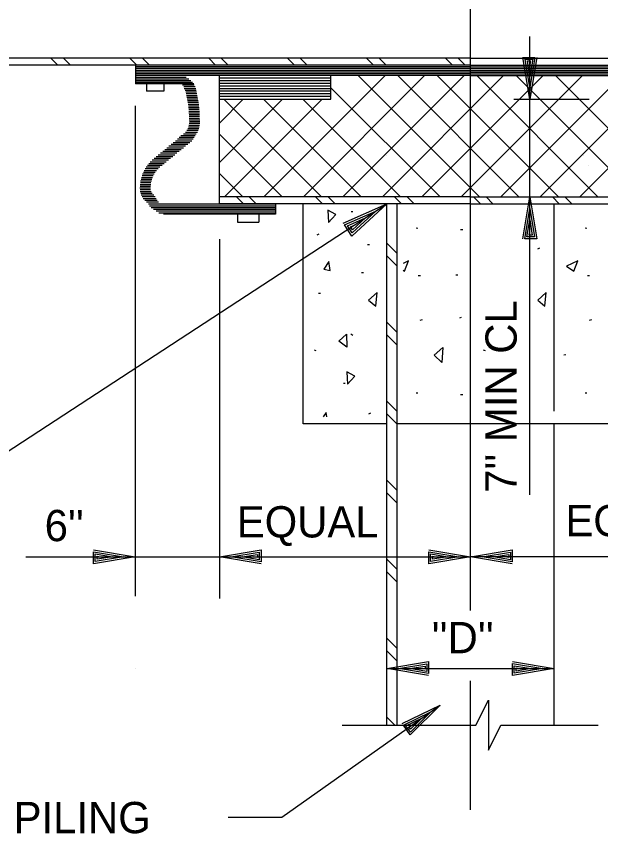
# Model space of a CAD drawing. Extents: x 22339.2 to 22413.4, y 22369.6 to 22418.8.
# Drawn here: x 22343.24 to 22346.729, y 22391.783 to 22396.66 of the extents above; entities that cross this region are included whole.
import ezdxf

# ---------------------------------------------------------------- set-up
doc = ezdxf.new("R2010")
doc.units = 0
for name, color, linetype in [('Level 1', 7, 'Continuous'), ('Level 10', 7, 'Continuous'), ('Level 2', 7, 'Continuous'), ('Level 4', 7, 'Continuous'), ('Level 44', 7, 'Continuous'), ('Level 7', 7, 'Continuous'), ('Level 8', 7, 'Continuous')]:
    doc.layers.add(name, color=color, linetype=linetype)

msp = doc.modelspace()

# ---------------------------------------------------------------- linework, layer by layer
at = {"layer": 'Level 1'}
for p, q in [((22345.9524, 22393.1147), (22345.9524, 22402.6063)), ((22346.3062, 22396.1656), (22346.3062, 22396.54)), ((22344.4524, 22395.5406), (22344.4524, 22396.3063)), ((22345.1191, 22396.2906), (22344.4524, 22396.2906)), ((22345.1191, 22396.275), (22344.4524, 22396.275)), ((22345.1191, 22396.2594), (22344.4524, 22396.2594)), ((22344.0172, 22396.2566), (22344.0172, 22396.2136)), ((22344.1208, 22396.2136), (22344.0172, 22396.2136)), ((22344.1208, 22396.2566), (22344.1208, 22396.2136)), ((22345.1191, 22396.2438), (22344.4524, 22396.2438)), ((22345.1191, 22396.2281), (22344.4524, 22396.2281)), ((22345.1191, 22396.2125), (22344.4524, 22396.2125)), ((22345.1191, 22396.1969), (22344.4524, 22396.1969)), ((22345.1191, 22396.1813), (22344.4524, 22396.1813)), ((22346.2105, 22396.1656), (22346.6612, 22396.1656)), ((22346.3062, 22395.5823), (22346.3062, 22396.1656)), ((22343.9502, 22396.1261), (22343.9502, 22393.1991)), ((22346.3062, 22396.1448), (22346.3062, 22396.1448)), ((22346.3062, 22395.8948), (22346.3062, 22395.8948)), ((22345.4524, 22395.8323), (22345.4524, 22395.8323)), ((22346.3062, 22395.8255), (22346.3062, 22395.8255)), ((22346.6267, 22395.8323), (22346.6267, 22395.8323)), ((22345.3966, 22395.7912), (22345.3966, 22395.7912)), ((22346.6566, 22395.7697), (22346.6566, 22395.7697)), ((22345.9524, 22395.5823), (22344.4524, 22395.5823)), ((22345.9524, 22395.5823), (22347.4524, 22395.5823)), ((22346.3062, 22393.8053), (22346.3062, 22395.5823)), ((22345.9524, 22395.5406), (22344.4524, 22395.5406)), ((22345.9524, 22395.5406), (22347.4524, 22395.5406)), ((22344.5612, 22395.479), (22344.5612, 22395.4313)), ((22344.6886, 22395.479), (22344.6886, 22395.4313)), ((22344.5612, 22395.4313), (22344.6886, 22395.4313)), ((22344.4524, 22395.3296), (22344.4524, 22393.1868)), ((22343.2972, 22393.4347), (22343.9502, 22393.4347)), ((22343.9502, 22393.4347), (22344.4524, 22393.4347)), ((22344.4524, 22393.4347), (22345.9524, 22393.4347)), ((22344.4524, 22393.4347), (22344.4524, 22393.4347)), ((22344.5217, 22393.4347), (22344.5217, 22393.4347)), ((22345.8831, 22393.4347), (22345.8831, 22393.4347)), ((22347.4524, 22393.4347), (22345.9524, 22393.4347)), ((22345.9524, 22393.4347), (22345.9524, 22393.4347)), ((22345.9524, 22393.4347), (22345.9524, 22393.4347)), ((22346.0217, 22393.4347), (22346.0217, 22393.4347)), ((22343.9502, 22392.768), (22343.9502, 22392.768)), ((22345.4524, 22392.768), (22346.4524, 22392.768)), ((22345.8831, 22392.768), (22345.8831, 22392.768)), ((22345.9524, 22392.768), (22345.9524, 22392.768)), ((22345.9524, 22392.768), (22345.9524, 22392.768)), ((22346.0217, 22392.768), (22346.0217, 22392.768)), ((22345.9524, 22391.9249), (22345.9524, 22392.6957)), ((22345.7149, 22392.5096), (22345.7149, 22392.5096)), ((22345.7715, 22392.5496), (22345.7715, 22392.5496)), ((22345.1864, 22392.4303), (22345.9844, 22392.4303)), ((22346.1339, 22392.4303), (22346.7136, 22392.4303))]:
    msp.add_line(p, q, dxfattribs=at)
msp.add_lwpolyline([(22345.9844, 22392.4303), (22346.0589, 22392.5803), (22346.0589, 22392.2806), (22346.1339, 22392.4303)], dxfattribs=at)
at = {"layer": 'Level 10'}
for p, q in [((22342.4783, 22393.5993), (22345.4524, 22395.5406)), ((22345.4524, 22395.5406), (22345.4524, 22395.5406)), ((22345.3871, 22395.498), (22345.3871, 22395.498))]:
    msp.add_line(p, q, dxfattribs=at)
msp.add_lwpolyline([(22345.1921, 22395.4262), (22345.4524, 22395.5406), (22345.2429, 22395.3484), (22345.1995, 22395.4149), (22345.3871, 22395.498), (22345.2448, 22395.3675), (22345.2169, 22395.4102), (22345.3243, 22395.457), (22345.2466, 22395.3866), (22345.2352, 22395.4042), (22345.259, 22395.4144)], dxfattribs=at)
at = {"layer": 'Level 2'}
for p, q in [((22345.9524, 22396.4104), (22339.2566, 22396.4104)), ((22345.9524, 22396.4104), (22352.6356, 22396.4104)), ((22345.9524, 22396.3688), (22339.2869, 22396.3688)), ((22343.9511, 22396.3688), (22343.9511, 22396.2566)), ((22345.9524, 22396.3583), (22343.9511, 22396.3583)), ((22345.9524, 22396.3688), (22352.6121, 22396.3688)), ((22345.9524, 22396.3583), (22347.9537, 22396.3583)), ((22345.9524, 22396.3479), (22343.9511, 22396.3479)), ((22345.9524, 22396.3375), (22343.9511, 22396.3375)), ((22345.9524, 22396.3271), (22343.9511, 22396.3271)), ((22345.9524, 22396.3167), (22343.9511, 22396.3167)), ((22345.9524, 22396.3063), (22343.9511, 22396.3063)), ((22344.4524, 22396.1656), (22344.4524, 22396.3063)), ((22345.1191, 22396.1656), (22345.1191, 22396.3063)), ((22345.9524, 22396.3479), (22347.9537, 22396.3479)), ((22345.9524, 22396.3375), (22347.9537, 22396.3375)), ((22345.9524, 22396.3271), (22347.9537, 22396.3271)), ((22345.9524, 22396.3167), (22347.9537, 22396.3167)), ((22345.9524, 22396.3063), (22347.9537, 22396.3063)), ((22344.2992, 22396.2566), (22343.9511, 22396.2566)), ((22344.4524, 22396.1656), (22345.1191, 22396.1656)), ((22344.7869, 22395.5406), (22344.7869, 22395.479)), ((22345.4524, 22392.4303), (22345.4524, 22395.5406)), ((22345.5149, 22392.4303), (22345.5149, 22395.5406)), ((22346.4524, 22394.3032), (22346.4524, 22395.5406)), ((22344.7869, 22395.479), (22344.1184, 22395.479)), ((22346.4524, 22392.4303), (22346.4524, 22394.2281))]:
    msp.add_line(p, q, dxfattribs=at)
for points in [[(22346.3475, 22396.415), (22346.3062, 22396.1656), (22346.2648, 22396.415), (22346.3355, 22396.415), (22346.3062, 22396.235), (22346.2782, 22396.4043), (22346.3235, 22396.4043), (22346.3062, 22396.3016), (22346.2915, 22396.3936), (22346.3102, 22396.3936), (22346.3062, 22396.371)], [(22344.2344, 22396.3063), (22343.9511, 22396.3063)], [(22344.2549, 22396.2958), (22343.9524, 22396.2958)], [(22344.2702, 22396.2854), (22343.9524, 22396.2854)], [(22344.2826, 22396.275), (22343.9524, 22396.275)], [(22344.2929, 22396.2646), (22343.9524, 22396.2646)], [(22344.3024, 22396.249), (22344.2327, 22396.249)], [(22344.3077, 22396.2386), (22344.2408, 22396.2386)], [(22344.3111, 22396.2281), (22344.2424, 22396.2281)], [(22344.3139, 22396.2177), (22344.2487, 22396.2177)], [(22344.3163, 22396.2073), (22344.2519, 22396.2073)], [(22344.3183, 22396.1969), (22344.2544, 22396.1969)], [(22344.32, 22396.1865), (22344.2566, 22396.1865)], [(22344.3218, 22396.1761), (22344.2584, 22396.1761)], [(22344.3236, 22396.1656), (22344.2602, 22396.1656)], [(22344.3254, 22396.1552), (22344.2619, 22396.1552)], [(22344.3273, 22396.1448), (22344.2638, 22396.1448)], [(22344.329, 22396.1344), (22344.2656, 22396.1344)], [(22344.3305, 22396.124), (22344.2673, 22396.124)], [(22344.3317, 22396.1136), (22344.2687, 22396.1136)], [(22344.3324, 22396.1031), (22344.2698, 22396.1031)], [(22344.333, 22396.0927), (22344.2704, 22396.0927)], [(22344.3336, 22396.0823), (22344.271, 22396.0823)], [(22344.3342, 22396.0719), (22344.2716, 22396.0719)], [(22344.3349, 22396.0511), (22344.2719, 22396.0511)], [(22344.3347, 22396.0615), (22344.2722, 22396.0615)], [(22344.3354, 22396.0198), (22344.2726, 22396.0198)], [(22344.3357, 22396.0406), (22344.2731, 22396.0406)], [(22344.3359, 22396.0302), (22344.2734, 22396.0302)], [(22344.3226, 22395.9677), (22344.2504, 22395.9677)], [(22344.3266, 22395.9781), (22344.2578, 22395.9781)], [(22344.3298, 22395.9886), (22344.2634, 22395.9886)], [(22344.3324, 22395.999), (22344.2677, 22395.999)], [(22344.3342, 22396.0094), (22344.2707, 22396.0094)], [(22344.2875, 22395.9156), (22344.1901, 22395.9156)], [(22344.297, 22395.9261), (22344.2029, 22395.9261)], [(22344.3012, 22395.9365), (22344.2117, 22395.9365)], [(22344.3083, 22395.9469), (22344.2231, 22395.9469)], [(22344.3139, 22395.9573), (22344.2387, 22395.9573)], [(22344.2379, 22395.874), (22344.139, 22395.874)], [(22344.2507, 22395.8844), (22344.1518, 22395.8844)], [(22344.2634, 22395.8948), (22344.1646, 22395.8948)], [(22344.2762, 22395.9052), (22344.1774, 22395.9052)], [(22344.1741, 22395.8219), (22344.0752, 22395.8219)], [(22344.1868, 22395.8323), (22344.088, 22395.8323)], [(22344.198, 22395.8427), (22344.1005, 22395.8427)], [(22344.2125, 22395.8531), (22344.1153, 22395.8531)], [(22344.2251, 22395.8636), (22344.1263, 22395.8636)], [(22344.1102, 22395.7698), (22344.023, 22395.7698)], [(22344.123, 22395.7802), (22344.0311, 22395.7802)], [(22344.1358, 22395.7906), (22344.0402, 22395.7906)], [(22344.1485, 22395.8011), (22344.0506, 22395.8011)], [(22344.1613, 22395.8115), (22344.0625, 22395.8115)], [(22344.0701, 22395.7281), (22343.9987, 22395.7281)], [(22344.0778, 22395.7386), (22344.0037, 22395.7386)], [(22344.0869, 22395.749), (22344.0094, 22395.749)], [(22344.0977, 22395.7594), (22344.0158, 22395.7594)], [(22344.0465, 22395.6761), (22343.9825, 22395.6761)], [(22344.0495, 22395.6865), (22343.9847, 22395.6865)], [(22344.0533, 22395.6969), (22343.9874, 22395.6969)], [(22344.058, 22395.7073), (22343.9906, 22395.7073)], [(22344.0635, 22395.7177), (22343.9944, 22395.7177)], [(22344.0411, 22395.6344), (22343.9786, 22395.6344)], [(22344.0415, 22395.6448), (22343.9789, 22395.6448)], [(22344.0415, 22395.624), (22343.9789, 22395.624)], [(22344.0425, 22395.6552), (22343.9796, 22395.6552)], [(22344.0441, 22395.6656), (22343.9808, 22395.6656)], [(22344.0446, 22395.6136), (22343.9796, 22395.6136)], [(22344.0518, 22395.6031), (22343.9834, 22395.6031)], [(22344.0615, 22395.5927), (22343.986, 22395.5927)], [(22344.0686, 22395.5823), (22343.9918, 22395.5823)], [(22346.2648, 22395.333), (22346.3062, 22395.5823), (22346.3475, 22395.333), (22346.2768, 22395.333), (22346.3062, 22395.513), (22346.3342, 22395.3436), (22346.2888, 22395.3436), (22346.3062, 22395.4463), (22346.3208, 22395.3543), (22346.3022, 22395.3543), (22346.3062, 22395.377)], [(22344.075, 22395.5719), (22343.9982, 22395.5719)], [(22344.0808, 22395.5615), (22344.0073, 22395.5615)], [(22344.0898, 22395.5511), (22344.0176, 22395.5511)], [(22344.7857, 22395.5384), (22344.0299, 22395.5384)], [(22344.7857, 22395.528), (22344.0363, 22395.528)], [(22344.7857, 22395.5176), (22344.0449, 22395.5176)], [(22344.7857, 22395.5072), (22344.0601, 22395.5072)], [(22344.7857, 22395.4968), (22344.0759, 22395.4968)], [(22344.7857, 22395.4864), (22344.0912, 22395.4864)], [(22343.7008, 22393.476), (22343.9502, 22393.4347), (22343.7008, 22393.3933), (22343.7008, 22393.464), (22343.8808, 22393.4347), (22343.7115, 22393.4067), (22343.7115, 22393.452), (22343.8142, 22393.4347), (22343.7222, 22393.42), (22343.7222, 22393.4387), (22343.7448, 22393.4347)], [(22344.7017, 22393.3933), (22344.4524, 22393.4347), (22344.7017, 22393.476), (22344.7017, 22393.4053), (22344.5217, 22393.4347), (22344.6911, 22393.4627), (22344.6911, 22393.4173), (22344.5884, 22393.4347), (22344.6804, 22393.4493), (22344.6804, 22393.4307), (22344.6577, 22393.4347)], [(22345.7031, 22393.476), (22345.9524, 22393.4347), (22345.7031, 22393.3933), (22345.7031, 22393.464), (22345.8831, 22393.4347), (22345.7137, 22393.4067), (22345.7137, 22393.452), (22345.8164, 22393.4347), (22345.7244, 22393.42), (22345.7244, 22393.4387), (22345.7471, 22393.4347)], [(22346.2017, 22393.3933), (22345.9524, 22393.4347), (22346.2017, 22393.476), (22346.2017, 22393.4053), (22346.0217, 22393.4347), (22346.1911, 22393.4627), (22346.1911, 22393.4173), (22346.0884, 22393.4347), (22346.1804, 22393.4493), (22346.1804, 22393.4307), (22346.1577, 22393.4347)], [(22345.7017, 22392.7267), (22345.4524, 22392.768), (22345.7017, 22392.8093), (22345.7017, 22392.7387), (22345.5217, 22392.768), (22345.6911, 22392.796), (22345.6911, 22392.7507), (22345.5884, 22392.768), (22345.6804, 22392.7827), (22345.6804, 22392.764), (22345.6577, 22392.768)], [(22346.2031, 22392.8093), (22346.4524, 22392.768), (22346.2031, 22392.7267), (22346.2031, 22392.7973), (22346.3831, 22392.768), (22346.2137, 22392.74), (22346.2137, 22392.7853), (22346.3164, 22392.768), (22346.2244, 22392.7533), (22346.2244, 22392.772), (22346.2471, 22392.768)], [(22344.506, 22391.881), (22344.8265, 22391.881), (22345.7715, 22392.5496)], [(22345.5441, 22392.4393), (22345.7715, 22392.5496), (22345.5919, 22392.3719), (22345.5511, 22392.4296), (22345.7149, 22392.5096), (22345.5929, 22392.3889), (22345.5667, 22392.4259), (22345.6605, 22392.4711), (22345.5939, 22392.4059), (22345.5831, 22392.4212), (22345.6039, 22392.431)]]:
    msp.add_lwpolyline(points, dxfattribs=at)
at = {"layer": 'Level 44'}
for p, q in [((22345.2486, 22395.4929), (22345.2386, 22395.4937)), ((22345.6372, 22395.3942), (22345.6272, 22395.396)), ((22345.9062, 22395.3857), (22345.8927, 22395.3857)), ((22346.6472, 22395.3942), (22346.6372, 22395.396)), ((22345.0458, 22395.3592), (22345.0338, 22395.3532)), ((22345.3498, 22395.2963), (22345.3363, 22395.2963)), ((22346.3642, 22395.2765), (22346.3522, 22395.2705)), ((22345.3141, 22395.1286), (22345.3006, 22395.1286)), ((22345.6532, 22395.1105), (22345.6397, 22395.1105)), ((22345.8772, 22395.1152), (22345.8644, 22395.1152)), ((22346.6632, 22395.1105), (22346.6497, 22395.1105)), ((22345.0571, 22395.0056), (22345.0436, 22395.0056)), ((22345.6639, 22394.8487), (22345.6504, 22394.845)), ((22345.8969, 22394.8622), (22345.8872, 22394.8585)), ((22346.6739, 22394.8487), (22346.6604, 22394.845)), ((22345.2489, 22394.7562), (22345.2377, 22394.763)), ((22345.0312, 22394.6632), (22345.0204, 22394.6682)), ((22346.0412, 22394.6632), (22346.0304, 22394.6682)), ((22346.5209, 22394.6392), (22346.5099, 22394.6382)), ((22345.2039, 22394.469), (22345.1939, 22394.4697)), ((22345.6372, 22394.4105), (22345.6272, 22394.4122)), ((22346.6472, 22394.4105), (22346.6372, 22394.4122)), ((22345.9062, 22394.402), (22345.8927, 22394.402)), ((22345.3542, 22394.2927), (22345.3422, 22394.2867))]:
    msp.add_line(p, q, dxfattribs=at)
for points in [[(22345.1045, 22395.4291), (22345.1472, 22395.4771), (22345.0995, 22395.5026)], [(22345.1138, 22395.143), (22345.1068, 22395.1977), (22345.076, 22395.152)], [(22346.5687, 22395.1397), (22346.5924, 22395.201), (22346.5262, 22395.1687)], [(22345.3947, 22395.0115), (22345.3434, 22394.9667), (22345.3859, 22394.931)], [(22346.4047, 22395.0115), (22346.3534, 22394.9667), (22346.3959, 22394.931)], [(22345.2134, 22394.6855), (22345.1654, 22394.7217), (22345.2114, 22394.7625)], [(22345.7812, 22394.5952), (22345.7349, 22394.638), (22345.7862, 22394.6837)], [(22345.2184, 22394.4655), (22345.2612, 22394.5135), (22345.2134, 22394.539)]]:
    msp.add_lwpolyline(points, close=True, dxfattribs=at)
for points in [[(22345.5501, 22395.1455), (22345.5587, 22395.1397), (22345.5824, 22395.201), (22345.5501, 22395.1852)], [(22345.0945, 22394.2705), (22345.0912, 22394.2967), (22345.0733, 22394.2701)]]:
    msp.add_lwpolyline(points, dxfattribs=at)
at = {"layer": 'Level 7'}
for p, q in [((22344.9524, 22394.2281), (22344.9524, 22395.5406)), ((22345.4524, 22394.2281), (22344.9524, 22394.2281)), ((22346.9524, 22394.2281), (22345.5149, 22394.2281))]:
    msp.add_line(p, q, dxfattribs=at)
at = {"layer": 'Level 8'}
for p, q in [((22346.3062, 22396.235), (22346.3062, 22396.235)), ((22346.3062, 22396.1656), (22346.3062, 22396.1656)), ((22346.3062, 22395.5823), (22346.3062, 22395.5823)), ((22346.3062, 22395.513), (22346.3062, 22395.513)), ((22343.8808, 22393.4347), (22343.8808, 22393.4347)), ((22343.9502, 22393.4347), (22343.9502, 22393.4347)), ((22344.4524, 22393.4347), (22344.4524, 22393.4347)), ((22344.5217, 22393.4347), (22344.5217, 22393.4347)), ((22345.8831, 22393.4347), (22345.8831, 22393.4347)), ((22345.9524, 22393.4347), (22345.9524, 22393.4347)), ((22345.9524, 22393.4347), (22345.9524, 22393.4347)), ((22346.0217, 22393.4347), (22346.0217, 22393.4347)), ((22345.4524, 22392.768), (22345.4524, 22392.768)), ((22345.5217, 22392.768), (22345.5217, 22392.768)), ((22346.3831, 22392.768), (22346.3831, 22392.768)), ((22346.4524, 22392.768), (22346.4524, 22392.768))]:
    msp.add_line(p, q, dxfattribs=at)
for points in [[(22343.4876, 22396.3688), (22343.4459, 22396.4104)], [(22343.563, 22396.3688), (22343.5214, 22396.4104)], [(22343.959, 22396.3688), (22343.9173, 22396.4104)], [(22344.0344, 22396.3688), (22343.9928, 22396.4104)], [(22344.4304, 22396.3688), (22344.3887, 22396.4104)], [(22344.5058, 22396.3688), (22344.4642, 22396.4104)], [(22344.9018, 22396.3688), (22344.8602, 22396.4104)], [(22344.9772, 22396.3688), (22344.9356, 22396.4104)], [(22345.3732, 22396.3688), (22345.3315, 22396.4104)], [(22345.4486, 22396.3688), (22345.407, 22396.4104)], [(22345.8446, 22396.3688), (22345.803, 22396.4104)], [(22345.92, 22396.3688), (22345.8784, 22396.4104)], [(22344.7186, 22395.5823), (22345.4425, 22396.3063)], [(22344.9543, 22395.5823), (22345.6782, 22396.3063)], [(22345.19, 22395.5823), (22345.9139, 22396.3063)], [(22346.0059, 22395.5823), (22345.2819, 22396.3063)], [(22345.4257, 22395.5823), (22346.1497, 22396.3063)], [(22346.2416, 22395.5823), (22345.5176, 22396.3063)], [(22345.6614, 22395.5823), (22346.3854, 22396.3063)], [(22346.4773, 22395.5823), (22345.7533, 22396.3063)], [(22345.8971, 22395.5823), (22346.6211, 22396.3063)], [(22346.713, 22395.5823), (22345.989, 22396.3063)], [(22346.9487, 22395.5823), (22346.2247, 22396.3063)], [(22347.1844, 22395.5823), (22346.4604, 22396.3063)], [(22345.7702, 22395.5823), (22345.1191, 22396.2334)], [(22346.1328, 22395.5823), (22346.7857, 22396.2352)], [(22344.4524, 22395.7875), (22344.8305, 22396.1656)], [(22344.4524, 22396.0232), (22344.5948, 22396.1656)], [(22345.0631, 22395.5823), (22344.4797, 22396.1656)], [(22344.4829, 22395.5823), (22345.0662, 22396.1656)], [(22345.2987, 22395.5823), (22344.7154, 22396.1656)], [(22345.5345, 22395.5823), (22344.9511, 22396.1656)], [(22346.3685, 22395.5823), (22346.9518, 22396.1656)], [(22346.6042, 22395.5823), (22347.1875, 22396.1656)], [(22344.8274, 22395.5823), (22344.4524, 22395.9572)], [(22344.5917, 22395.5823), (22344.4524, 22395.7215)], [(22344.5968, 22395.5406), (22344.5551, 22395.5823)], [(22344.6722, 22395.5406), (22344.6305, 22395.5823)], [(22345.0682, 22395.5406), (22345.0265, 22395.5823)], [(22345.1436, 22395.5406), (22345.1019, 22395.5823)], [(22345.5396, 22395.5406), (22345.4979, 22395.5823)], [(22345.615, 22395.5406), (22345.5733, 22395.5823)], [(22346.011, 22395.5406), (22345.9693, 22395.5823)], [(22346.0864, 22395.5406), (22346.0447, 22395.5823)], [(22346.4824, 22395.5406), (22346.4407, 22395.5823)], [(22346.5578, 22395.5406), (22346.5161, 22395.5823)], [(22345.5149, 22395.2444), (22345.4524, 22395.3069)], [(22345.5149, 22395.169), (22345.4524, 22395.2315)], [(22345.5149, 22394.773), (22345.4524, 22394.8355)], [(22345.5149, 22394.6976), (22345.4524, 22394.7601)], [(22345.5149, 22394.3016), (22345.4524, 22394.3641)], [(22345.5149, 22394.2262), (22345.4524, 22394.2887)], [(22345.5149, 22393.8302), (22345.4524, 22393.8927)], [(22345.5149, 22393.7548), (22345.4524, 22393.8173)], [(22345.5149, 22393.3588), (22345.4524, 22393.4213)], [(22345.5149, 22393.2834), (22345.4524, 22393.3459)], [(22345.5149, 22392.8874), (22345.4524, 22392.9499)], [(22345.5149, 22392.812), (22345.4524, 22392.8745)], [(22345.5007, 22392.4303), (22345.4524, 22392.4785)]]:
    msp.add_lwpolyline(points, dxfattribs=at)

# ---------------------------------------------------------------- texts
at = {"layer": 'Level 4'}
msp.add_text("7'' MIN CL ", height=0.186667, rotation=90, dxfattribs=at).set_placement((22346.2278, 22393.816))
for s, height, p in [('EQUAL', 0.18667, (22344.5567, 22393.5504)), ('EQUAL', 0.18667, (22346.5193, 22393.5573)), ("6''", 0.18667, (22343.4094, 22393.5281)), ("''D''", 0.18667, (22345.72, 22392.8595)), ('STEEL SHEET PILING', 0.186667, (22341.4626, 22391.7856))]:
    msp.add_text(s, height=height, dxfattribs=at).set_placement(p)

doc.saveas('drawing.dxf')
